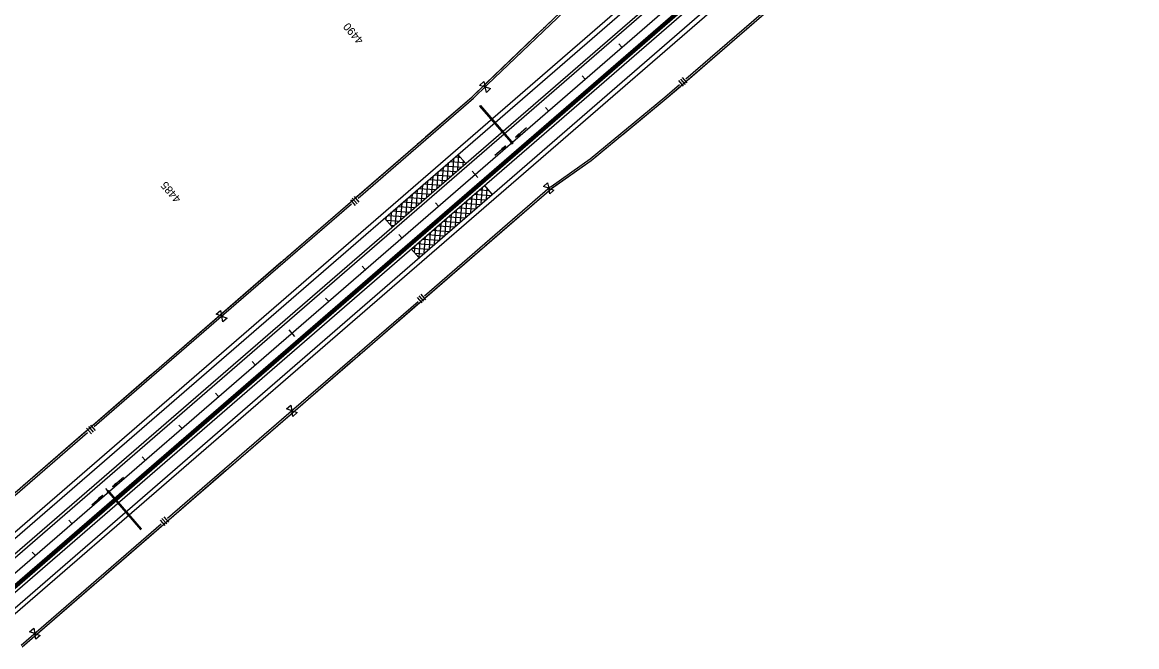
# Model space of a CAD drawing. Extents: x 192699 to 285914, y 194342 to 233219.
# Drawn here: x 198915 to 201213, y 198895 to 200182 of the extents above; entities that cross this region are included whole.
import ezdxf

# ---------------------------------------------------------------- set-up
doc = ezdxf.new("R2010")
doc.units = 0
for name, color, linetype in [('CENT LINE', 7, 'Continuous'), ('CONCRETE', 7, 'Continuous'), ('DRAINAGE', 7, 'Continuous'), ('DRAINAGE ARROWS', 7, 'Continuous'), ('PAVEMENT TRANSITION', 7, 'Continuous'), ('R-W - CofA', 7, 'Continuous'), ('R_Water Annot', 7, 'Continuous'), ('ROAD', 7, 'Continuous'), ('SHOULDER', 7, 'Continuous'), ('STATIONING1', 7, 'Continuous'), ('WRSF', 7, 'Continuous')]:
    doc.layers.add(name, color=color, linetype=linetype)

msp = doc.modelspace()

# ---------------------------------------------------------------- linework, layer by layer
at = {"layer": 'CENT LINE'}
msp.add_line((198833.2, 198989.9), (207514.6, 206505.5), dxfattribs=at)
at = {"layer": 'CONCRETE'}
for p, q in [((198845, 198976.3), (202641.5, 202263)), ((198847.6, 198973.2), (202644.1, 202259.9))]:
    msp.add_line(p, q, dxfattribs=at)
at = {"layer": 'DRAINAGE'}
for p, q in [((199093.3, 199212.4), (199158.8, 199136.8)), ((199094.8, 199213.7), (199160.3, 199138.1)), ((199158, 199136.2), (199161, 199138.8))]:
    msp.add_line(p, q, dxfattribs=at)
for points in [[(199858.2, 200009.5), (199859.7, 200010.8)], [(199858.2, 200009.5), (199922.3, 199935.4)], [(199859.7, 200010.8), (199923.8, 199936.7)]]:
    msp.add_lwpolyline(points, dxfattribs=at)
for points in [[(199924.2, 199931.7), (199927.2, 199934.3), (199924.6, 199937.4), (199921.6, 199934.8)], [(199092.5, 199211.8), (199095.6, 199214.4), (199093, 199217.4), (199089.9, 199214.8)]]:
    msp.add_lwpolyline(points, close=True, dxfattribs=at)
at = {"layer": 'DRAINAGE ARROWS'}
for p, q in [((199938.9, 199952.8), (199932.3, 199945.2)), ((199940.9, 199950.6), (199932.3, 199945.2)), ((199939.1, 199952.7), (199933.6, 199946.2)), ((199940.7, 199950.8), (199933.6, 199946.2)), ((199939.2, 199952.5), (199934.9, 199947.4)), ((199940.5, 199951), (199934.9, 199947.4)), ((199939.4, 199952.3), (199936.1, 199948.5)), ((199940.4, 199951.2), (199936.1, 199948.5)), ((199939.6, 199952.1), (199937.4, 199949.6)), ((199940.2, 199951.3), (199937.4, 199949.6)), ((199939.7, 199951.9), (199938.7, 199950.7)), ((199940, 199951.5), (199938.7, 199950.7)), ((199940.9, 199950.6), (199938.9, 199952.8)), ((199903.9, 199922.5), (199912.4, 199927.9)), ((199905.8, 199920.3), (199903.9, 199922.5)), ((199904, 199922.3), (199911.2, 199926.8)), ((199904.2, 199922.2), (199909.9, 199925.7)), ((199904.4, 199922), (199908.6, 199924.6)), ((199904.5, 199921.8), (199907.3, 199923.5)), ((199904.7, 199921.6), (199906.1, 199922.4)), ((199905, 199921.2), (199906.1, 199922.4)), ((199905.2, 199921), (199907.3, 199923.5)), ((199905.3, 199920.8), (199908.6, 199924.6)), ((199905.5, 199920.6), (199909.9, 199925.7)), ((199905.7, 199920.5), (199911.2, 199926.8)), ((199905.8, 199920.3), (199912.4, 199927.9)), ((199107.7, 199232.4), (199101.1, 199224.7)), ((199109.6, 199230.1), (199101.1, 199224.7)), ((199107.8, 199232.2), (199102.4, 199225.8)), ((199109.5, 199230.3), (199102.4, 199225.8)), ((199108, 199232), (199103.7, 199226.9)), ((199109.3, 199230.5), (199103.7, 199226.9)), ((199108.2, 199231.8), (199104.9, 199228)), ((199109.1, 199230.7), (199104.9, 199228)), ((199108.3, 199231.6), (199106.2, 199229.1)), ((199109, 199230.9), (199106.2, 199229.1)), ((199108.5, 199231.4), (199107.4, 199230.2)), ((199108.8, 199231.1), (199107.4, 199230.2)), ((199109.6, 199230.1), (199107.7, 199232.4)), ((199072.6, 199202.1), (199081.2, 199207.5)), ((199072.8, 199201.9), (199079.9, 199206.4)), ((199073, 199201.7), (199078.6, 199205.3)), ((199073.1, 199201.5), (199077.4, 199204.2)), ((199073.3, 199201.3), (199076.1, 199203.1)), ((199073.9, 199200.6), (199076.1, 199203.1)), ((199074.1, 199200.4), (199077.4, 199204.2)), ((199074.3, 199200.2), (199078.6, 199205.3)), ((199074.4, 199200), (199079.9, 199206.4)), ((199074.6, 199199.8), (199081.2, 199207.5)), ((199074.6, 199199.8), (199072.6, 199202.1)), ((199073.5, 199201.1), (199074.8, 199202)), ((199073.8, 199200.8), (199074.8, 199202))]:
    msp.add_line(p, q, dxfattribs=at)
at = {"layer": 'PAVEMENT TRANSITION'}
for p, q in [((199791.9, 199859.5), (199794.3, 199893.4)), ((199796.9, 199895.6), (199827.8, 199893.3)), ((199802.6, 199868.8), (199805, 199902.6)), ((199807.6, 199904.8), (199818.5, 199904)), ((199813.3, 199878), (199815.4, 199907.6)), ((199813.4, 199909.9), (199829.2, 199891.8)), ((199824, 199887.3), (199824.7, 199896.9)), ((199770.5, 199841), (199773, 199874.9)), ((199775.5, 199877.1), (199809.3, 199874.6)), ((199781.2, 199850.3), (199783.7, 199884.1)), ((199786.2, 199886.3), (199820, 199883.9)), ((199738.4, 199813.3), (199740.9, 199847.1)), ((199743.4, 199849.3), (199777.3, 199846.9)), ((199749.1, 199822.5), (199751.6, 199856.4)), ((199754.1, 199858.5), (199788, 199856.1)), ((199759.8, 199831.8), (199762.3, 199865.6)), ((199764.8, 199867.8), (199798.7, 199865.4)), ((199884.1, 199828.3), (199868.4, 199846.4)), ((199717.1, 199794.7), (199719.5, 199828.6)), ((199722, 199830.8), (199755.9, 199828.3)), ((199727.8, 199804), (199730.2, 199837.8)), ((199732.7, 199840), (199766.6, 199837.6)), ((199840.3, 199790.3), (199842.7, 199824.2)), ((199847.2, 199828), (199881, 199825.6)), ((199851, 199799.6), (199853.4, 199833.4)), ((199857.9, 199837.3), (199877.6, 199835.8)), ((199861.7, 199808.8), (199864.1, 199842.7)), ((199872.4, 199818.1), (199873.9, 199840)), ((199883.1, 199827.3), (199883.2, 199829.4)), ((199685, 199767), (199687.4, 199800.8)), ((199690, 199803), (199723.8, 199800.6)), ((199695.7, 199776.2), (199698.1, 199810.1)), ((199700.6, 199812.3), (199734.5, 199809.8)), ((199706.4, 199785.5), (199708.8, 199819.3)), ((199711.3, 199821.5), (199745.2, 199819.1)), ((199815.1, 199800.2), (199848.9, 199797.8)), ((199818.9, 199771.8), (199821.3, 199805.6)), ((199825.8, 199809.5), (199859.6, 199807.1)), ((199829.6, 199781.1), (199832, 199814.9)), ((199836.5, 199818.7), (199870.3, 199816.3)), ((199662.2, 199779), (199677.9, 199760.9)), ((199665.5, 199775.2), (199666, 199782.3)), ((199668.6, 199784.5), (199702.4, 199782.1)), ((199674.8, 199764.5), (199676.7, 199791.6)), ((199679.3, 199793.8), (199713.1, 199791.3)), ((199786.8, 199744), (199789.3, 199777.9)), ((199793.7, 199781.7), (199827.6, 199779.3)), ((199797.5, 199753.3), (199800, 199787.1)), ((199804.4, 199791), (199838.2, 199788.5)), ((199808.2, 199762.5), (199810.6, 199796.4)), ((199666, 199774.7), (199691.7, 199772.8)), ((199675.3, 199764), (199681, 199763.5)), ((199761.6, 199754), (199795.5, 199751.5)), ((199765.4, 199725.5), (199767.9, 199759.4)), ((199772.3, 199763.2), (199806.2, 199760.8)), ((199776.1, 199734.8), (199778.6, 199768.6)), ((199783, 199772.5), (199816.9, 199770)), ((199733.4, 199697.7), (199735.8, 199731.6)), ((199740.2, 199735.4), (199774.1, 199733)), ((199744.1, 199707), (199746.5, 199740.9)), ((199750.9, 199744.7), (199784.8, 199742.3)), ((199754.7, 199716.3), (199757.2, 199750.1)), ((199732.9, 199697.4), (199717.2, 199715.5)), ((199718.9, 199716.9), (199752.7, 199714.5)), ((199724, 199707.6), (199725.1, 199722.3)), ((199729.5, 199726.2), (199763.4, 199723.7)), ((199725.1, 199706.5), (199742, 199705.2))]:
    msp.add_line(p, q, dxfattribs=at)
at = {"layer": 'R-W - CofA'}
for p, q in [((199857.9, 200052.4), (199866.6, 200060.7)), ((199866.6, 200060.7), (199869.4, 200049.1)), ((200268.5, 200062.3), (200278.2, 200051.1)), ((200272.2, 200065.5), (200281.9, 200054.3)), ((200276, 200068.7), (200285.7, 200057.6)), ((199869.4, 200049.1), (199857.9, 200052.4)), ((199872.2, 200037.5), (199869.4, 200049.1)), ((199869.4, 200049.1), (199880.8, 200045.8)), ((199880.8, 200045.8), (199872.2, 200037.5)), ((199989.6, 199844.2), (199998.4, 199851.8)), ((199998.4, 199851.8), (200000.6, 199840.4)), ((199599.4, 199823.3), (199609.4, 199811.8)), ((200000.6, 199840.4), (199989.6, 199844.2)), ((200002.7, 199829), (200000.6, 199840.4)), ((200000.6, 199840.4), (200011.5, 199836.6)), ((200011.5, 199836.6), (200002.7, 199829)), ((199591.8, 199816.6), (199601.7, 199805.1)), ((199595.6, 199819.9), (199605.6, 199808.5)), ((199733, 199618.5), (199742.7, 199607.3)), ((199736.7, 199621.7), (199746.4, 199610.5)), ((199729.2, 199615.3), (199738.9, 199604.1)), ((199315, 199580.7), (199324.1, 199588.5)), ((199326.3, 199576.8), (199315, 199580.7)), ((199324.1, 199588.5), (199326.3, 199576.8)), ((199328.6, 199565), (199326.3, 199576.8)), ((199326.3, 199576.8), (199337.6, 199572.8)), ((199337.6, 199572.8), (199328.6, 199565)), ((199459.7, 199385.4), (199468.5, 199393)), ((199468.5, 199393), (199470.7, 199381.6)), ((199470.7, 199381.6), (199459.7, 199385.4)), ((199472.9, 199370.2), (199470.7, 199381.6)), ((199470.7, 199381.6), (199481.6, 199377.8)), ((199481.6, 199377.8), (199472.9, 199370.2)), ((199047.7, 199345.6), (199057.7, 199334.1)), ((199051.6, 199349), (199061.5, 199337.5)), ((199055.4, 199352.3), (199065.3, 199340.8)), ((199199.3, 199156.5), (199209, 199145.3)), ((199203.1, 199159.8), (199212.8, 199148.6)), ((199206.8, 199163), (199216.5, 199151.8)), ((198929.7, 198926.2), (198938.5, 198933.8)), ((198938.5, 198933.8), (198940.7, 198922.4)), ((198940.7, 198922.4), (198929.7, 198926.2)), ((198942.9, 198911), (198940.7, 198922.4)), ((198940.7, 198922.4), (198951.7, 198918.6)), ((198951.7, 198918.6), (198942.9, 198911))]:
    msp.add_line(p, q, dxfattribs=at)
for points in [[(198915, 198895.4), (200006.2, 199840), (200088.4, 199897.9), (200242.8, 200025.1), (200696.5, 200417.8), (200851, 200544.9), (200998.9, 200679.6), (203115.8, 202512.2), (203289.9, 202616.7), (203516.7, 202813), (203710.8, 203047.2)], [(198751.4, 199084.4), (199842.6, 200029.1), (200059.6, 200236.8), (200513.2, 200629.5), (200661.1, 200764.1), (200815.6, 200891.3), (201571.7, 201545.8), (201608, 201656.6), (201834.8, 201853), (202018.7, 201946.1), (202926, 202731.5), (203067.4, 202873.7)], [(199873.7, 200053.2), (200062.3, 200233.8), (200127.6, 200290.3)], [(200283.8, 200065.7), (200544.2, 200291.2)], [(199990.2, 200170.3), (199994.6, 200174.6)], [(199998.4, 200178.2), (200002.8, 200182.4)], [(200408, 200168), (200412.5, 200171.9)], [(200416.3, 200175.2), (200420.8, 200179.2)], [(199870.9, 200056.2), (199986.5, 200166.8)], [(200286.4, 200062.8), (200404.2, 200164.7)], [(199607.5, 199820.2), (199845.3, 200026.1), (199873.7, 200053.2)], [(199746.8, 199946.1), (199842.6, 200029.1), (199870.9, 200056.2)], [(200005.4, 199844.3), (200086, 199901.1), (200240.3, 200028.1), (200270.4, 200054.1)], [(200153.3, 199951.4), (200242.8, 200025.1), (200273, 200051.1)], [(199738.2, 199938.7), (199742.9, 199942.7)], [(200136.3, 199937.4), (200140.9, 199941.2)], [(200144.8, 199944.4), (200149.4, 199948.2)], [(199604.8, 199823.2), (199725.8, 199927.9)], [(199729.7, 199931.3), (199734.3, 199935.3)], [(200007.6, 199841.1), (200088.4, 199897.9), (200132.4, 199934.2)], [(199744.5, 199618.7), (200003.8, 199843.2), (200005.4, 199844.3)], [(199885.3, 199735.4), (200006.2, 199840), (200007.6, 199841.1)], [(199330.8, 199580.7), (199593.7, 199808.2)], [(199470.1, 199706.6), (199591.1, 199811.3)], [(199877, 199728.2), (199881.6, 199732.1)], [(199747.1, 199615.7), (199864.9, 199717.7)], [(199868.7, 199721), (199873.2, 199724.9)], [(199328.2, 199583.7), (199449.1, 199688.4)], [(199453, 199691.8), (199457.7, 199695.8)], [(199461.6, 199699.2), (199466.2, 199703.2)], [(199475.1, 199385.4), (199731.1, 199607.1)], [(199615.9, 199502.1), (199733.7, 199604.1)], [(199063.4, 199349.2), (199330.8, 199580.7)], [(199202.7, 199475.1), (199328.2, 199583.7)], [(199477.6, 199382.5), (199595.4, 199484.4)], [(199599.2, 199487.7), (199603.8, 199491.6)], [(199607.6, 199494.9), (199612.1, 199498.9)], [(199060.8, 199352.2), (199181.7, 199456.9)], [(199185.6, 199460.3), (199190.3, 199464.3)], [(199194.2, 199467.7), (199198.8, 199471.7)], [(199214.6, 199160), (199475.1, 199385.4)], [(199355.5, 199276.7), (199477.6, 199382.5)], [(198926.1, 199235.6), (199047, 199340.3)], [(198754, 199081.3), (199049.7, 199337.2)], [(199347.1, 199269.5), (199351.7, 199273.4)], [(199217.2, 199157), (199335, 199259)], [(199338.8, 199262.2), (199343.3, 199266.2)], [(198917.5, 199228.2), (198922.2, 199232.2)], [(198912.4, 198898.3), (199201.2, 199148.4)], [(199086, 199043.4), (199203.8, 199145.4)], [(198915, 198895.4), (199065.5, 199025.7)], [(199069.3, 199029), (199073.9, 199032.9)], [(199077.7, 199036.2), (199082.2, 199040.1)]]:
    msp.add_lwpolyline(points, dxfattribs=at)
at = {"layer": 'R_Water Annot'}
for p, q in [((199955, 199964.8), (199932.3, 199945.2)), ((199938.9, 199952.8), (199932.3, 199945.2)), ((199940.9, 199950.6), (199932.3, 199945.2)), ((199939.1, 199952.7), (199933.6, 199946.2)), ((199940.7, 199950.8), (199933.6, 199946.2)), ((199939.2, 199952.5), (199934.9, 199947.4)), ((199940.5, 199951), (199934.9, 199947.4)), ((199939.4, 199952.3), (199936.1, 199948.5)), ((199940.4, 199951.2), (199936.1, 199948.5)), ((199939.6, 199952.1), (199937.4, 199949.6)), ((199940.2, 199951.3), (199937.4, 199949.6)), ((199939.7, 199951.9), (199938.7, 199950.7)), ((199940, 199951.5), (199938.7, 199950.7)), ((199940.9, 199950.6), (199938.9, 199952.8)), ((199889.7, 199908.3), (199912.4, 199927.9)), ((199903.9, 199922.5), (199912.4, 199927.9)), ((199905.8, 199920.3), (199903.9, 199922.5)), ((199904, 199922.3), (199911.2, 199926.8)), ((199904.2, 199922.2), (199909.9, 199925.7)), ((199904.4, 199922), (199908.6, 199924.6)), ((199904.5, 199921.8), (199907.3, 199923.5)), ((199904.7, 199921.6), (199906.1, 199922.4)), ((199905, 199921.2), (199906.1, 199922.4)), ((199905.2, 199921), (199907.3, 199923.5)), ((199905.3, 199920.8), (199908.6, 199924.6)), ((199905.5, 199920.6), (199909.9, 199925.7)), ((199905.7, 199920.5), (199911.2, 199926.8)), ((199905.8, 199920.3), (199912.4, 199927.9)), ((199123.7, 199244.4), (199101.1, 199224.7)), ((199107.7, 199232.4), (199101.1, 199224.7)), ((199109.6, 199230.1), (199101.1, 199224.7)), ((199107.8, 199232.2), (199102.4, 199225.8)), ((199109.5, 199230.3), (199102.4, 199225.8)), ((199108, 199232), (199103.7, 199226.9)), ((199109.3, 199230.5), (199103.7, 199226.9)), ((199108.2, 199231.8), (199104.9, 199228)), ((199109.1, 199230.7), (199104.9, 199228)), ((199108.3, 199231.6), (199106.2, 199229.1)), ((199109, 199230.9), (199106.2, 199229.1)), ((199108.5, 199231.4), (199107.4, 199230.2)), ((199108.8, 199231.1), (199107.4, 199230.2)), ((199109.6, 199230.1), (199107.7, 199232.4)), ((199058.5, 199187.9), (199081.2, 199207.5)), ((199072.6, 199202.1), (199081.2, 199207.5)), ((199072.8, 199201.9), (199079.9, 199206.4)), ((199073, 199201.7), (199078.6, 199205.3)), ((199073.1, 199201.5), (199077.4, 199204.2)), ((199073.3, 199201.3), (199076.1, 199203.1)), ((199073.9, 199200.6), (199076.1, 199203.1)), ((199074.1, 199200.4), (199077.4, 199204.2)), ((199074.3, 199200.2), (199078.6, 199205.3)), ((199074.4, 199200), (199079.9, 199206.4)), ((199074.6, 199199.8), (199081.2, 199207.5)), ((199074.6, 199199.8), (199072.6, 199202.1)), ((199073.5, 199201.1), (199074.8, 199202)), ((199073.8, 199200.8), (199074.8, 199202))]:
    msp.add_line(p, q, dxfattribs=at)
at = {"layer": 'ROAD'}
for p, q in [((198797.8, 199030.7), (207479.2, 206546.3)), ((198813.5, 199012.5), (207494.9, 206528.2)), ((198852.8, 198967.2), (207534.2, 206482.8)), ((198868.5, 198949), (207549.9, 206464.7))]:
    msp.add_line(p, q, dxfattribs=at)
at = {"layer": 'SHOULDER'}
for p, q in [((198791.3, 199038.2), (202634.7, 202365.5)), ((198817.5, 199008), (202614, 202294.7)), ((198848.9, 198971.7), (202645.4, 202258.4)), ((198875.1, 198941.5), (202704.2, 202256.4))]:
    msp.add_line(p, q, dxfattribs=at)
at = {"layer": 'STATIONING1'}
for points in [[(200145.3, 200137.7), (200151.2, 200130.9)], [(200069.7, 200072.3), (200075.6, 200065.5)], [(199994.1, 200006.8), (200000, 200000)], [(199918.5, 199941.4), (199924.4, 199934.5)], [(199842.9, 199875.9), (199854.7, 199862.3)], [(199767.3, 199810.4), (199773.2, 199803.6)], [(199691.7, 199745), (199697.6, 199738.2)], [(199616.1, 199679.5), (199622, 199672.7)], [(199540.5, 199614.1), (199546.4, 199607.3)], [(199464.9, 199548.6), (199476.7, 199535)], [(199389.3, 199483.2), (199395.2, 199476.4)], [(199313.7, 199417.7), (199319.6, 199410.9)], [(199238.1, 199352.3), (199244, 199345.5)], [(199162.5, 199286.8), (199168.4, 199280)], [(199086.9, 199221.4), (199098.6, 199207.8)], [(199011.3, 199155.9), (199017.1, 199149.1)], [(198935.6, 199090.5), (198941.5, 199083.7)]]:
    msp.add_lwpolyline(points, dxfattribs=at)
at = {"layer": 'WRSF'}
msp.add_line((198846.3, 198974.7), (202676.8, 202290.9), dxfattribs=at)

# ---------------------------------------------------------------- texts
at = {"layer": 'STATIONING1'}
for s, p in [('4490', (199619.9, 200146)), ('4485', (199243.5, 199819))]:
    msp.add_text(s, height=16.5, rotation=130.8833, dxfattribs=at).set_placement(p)

doc.saveas('drawing.dxf')
